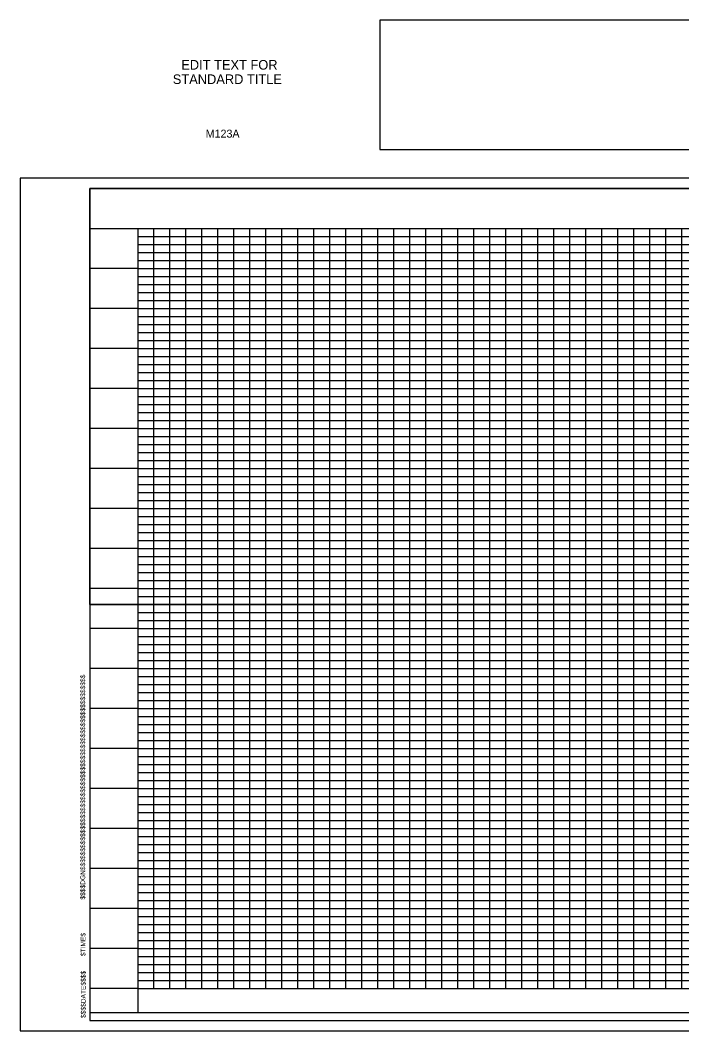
# Model space of a CAD drawing. Extents: x -87 to 1577, y -13 to 1250.
# Drawn here: x -87 to 740, y -13 to 1250 of the extents above; entities that cross this region are included whole.
import ezdxf

# ---------------------------------------------------------------- set-up
doc = ezdxf.new("R2010")
doc.units = 0
for name, color, linetype in [('D_CFL_Clip_Boundary_1', 7, 'Continuous'), ('D_CFL_Clip_Boundary_2', 7, 'Continuous'), ('D_CFL_Sheet_Border_ PlotShape', 7, 'Continuous'), ('D_CFL_Sheet_Border_Base', 7, 'Continuous'), ('D_CFL_Sheet_Border_Plan_Plan', 7, 'Continuous'), ('D_CFL_Sheet_Border_PnP', 7, 'Continuous'), ('D_CFL_Sheet_Border_Profile', 7, 'Continuous')]:
    doc.layers.add(name, color=color, linetype=linetype)

msp = doc.modelspace()

# ---------------------------------------------------------------- linework, layer by layer
at = {"layer": 'D_CFL_Clip_Boundary_1'}
msp.add_lwpolyline([(0, 520), (0, 1040), (1305, 1040), (1305, 1000), (1560, 1000), (1560, 520)], close=True, dxfattribs=at)
at = {"layer": 'D_CFL_Clip_Boundary_2'}
msp.add_lwpolyline([(1500, 520), (60, 520), (60, 40), (1500, 40)], close=True, dxfattribs=at)
at = {"layer": 'D_CFL_Sheet_Border_ PlotShape'}
msp.add_line((-86.9, -12.7), (-86.9, -12.7), dxfattribs=at)
msp.add_lwpolyline([(-86.9, -12.7), (1576.9, -12.7), (1576.9, 1052.6), (-86.9, 1052.6)], close=True, dxfattribs=at)
at = {"layer": 'D_CFL_Sheet_Border_Base'}
for points in [[(362.6, 1088.6), (1560, 1088.6), (1560, 1250.1), (362.6, 1250.1)], [(0, 0), (1560, 0), (1560, 1040), (0, 1040)]]:
    msp.add_lwpolyline(points, close=True, dxfattribs=at)
at = {"layer": 'D_CFL_Sheet_Border_Plan_Plan'}
msp.add_line((0, 520), (1560, 520), dxfattribs=at)
at = {"layer": 'D_CFL_Sheet_Border_PnP'}
for p, q in [((0, 520), (1560, 520)), ((60, 520), (60, 10)), ((80, 40), (80, 520)), ((100, 40), (100, 520)), ((120, 40), (120, 520)), ((140, 40), (140, 520)), ((160, 40), (160, 520)), ((180, 40), (180, 520)), ((200, 39.7), (200, 519.7)), ((220, 39.7), (220, 519.7)), ((240, 39.7), (240, 519.7)), ((260, 39.7), (260, 519.7)), ((280, 40), (280, 520)), ((300, 39.7), (300, 519.7)), ((320, 39.7), (320, 519.7)), ((340, 39.7), (340, 519.7)), ((360, 39.7), (360, 519.7)), ((380, 40), (380, 520)), ((400, 39.7), (400, 519.7)), ((420, 39.7), (420, 519.7)), ((440, 39.7), (440, 519.7)), ((460, 39.7), (460, 519.7)), ((480, 40), (480, 520)), ((500, 39.7), (500, 519.7)), ((520, 39.7), (520, 519.7)), ((540, 39.7), (540, 519.7)), ((560, 39.7), (560, 519.7)), ((580, 40), (580, 520)), ((600, 39.7), (600, 519.7)), ((620, 39.7), (620, 519.7)), ((640, 39.7), (640, 519.7)), ((660, 39.7), (660, 519.7)), ((680, 40), (680, 520)), ((700, 39.7), (700, 519.7)), ((720, 39.7), (720, 519.7)), ((60, 510), (1500, 510)), ((60, 500), (1500, 500)), ((60, 490), (0, 490)), ((60, 490), (1500, 490)), ((60, 480), (1500, 480)), ((60, 470), (1500, 470)), ((60, 460), (1500, 460)), ((60, 450), (1500, 450)), ((60, 440), (0, 440)), ((60, 440), (1500, 440)), ((60, 430), (1500, 430)), ((60, 420), (1500, 420)), ((60, 410), (1500, 410)), ((60, 400), (1500, 400)), ((60, 390), (0, 390)), ((60, 390), (1500, 390)), ((60, 380), (1500, 380)), ((60, 370), (1500, 370)), ((60, 360), (1500, 360)), ((60, 350), (1500, 350)), ((60, 340), (0, 340)), ((60, 340), (1500, 340)), ((60, 330), (1500, 330)), ((60, 320), (1500, 320)), ((60, 310), (1500, 310)), ((60, 300), (1500, 300)), ((60, 290), (0, 290)), ((60, 290), (1500, 290)), ((60, 280), (1500, 280)), ((60, 270), (1500, 270)), ((60, 260), (1500, 260)), ((60, 240), (0, 240)), ((60, 250), (1500, 250)), ((60, 240), (1500, 240)), ((60, 230), (1500, 230)), ((60, 220), (1500, 220)), ((60, 210), (1500, 210)), ((60, 190), (0, 190)), ((60, 200), (1500, 200)), ((60, 190), (1500, 190)), ((60, 180), (1500, 180)), ((60, 170), (1500, 170)), ((60, 160), (1500, 160)), ((60, 140), (0, 140)), ((60, 150), (1500, 150)), ((60, 140), (1500, 140)), ((60, 130), (1500, 130)), ((60, 120), (1500, 120)), ((60, 110), (1500, 110)), ((60, 90), (0, 90)), ((60, 100), (1500, 100)), ((60, 90), (1500, 90)), ((60, 80), (1500, 80)), ((60, 70), (1500, 70)), ((60, 60), (1500, 60)), ((60, 40), (0, 40)), ((60, 50), (1500, 50)), ((60, 40), (1500, 40)), ((0, 10), (1560, 10))]:
    msp.add_line(p, q, dxfattribs=at)
at = {"layer": 'D_CFL_Sheet_Border_Profile'}
for p, q in [((0, 990), (1560, 990)), ((60, 990), (60, 10)), ((80, 40), (80, 990)), ((100, 40), (100, 990)), ((120, 40), (120, 990)), ((140, 40), (140, 990)), ((160, 40), (160, 990)), ((180, 40), (180, 990)), ((200, 40), (200, 990)), ((220, 40), (220, 990)), ((240, 40), (240, 990)), ((260, 40), (260, 990)), ((280, 40), (280, 990)), ((300, 40), (300, 990)), ((320, 40), (320, 990)), ((340, 40), (340, 990)), ((360, 40), (360, 990)), ((380, 40), (380, 990)), ((400, 40), (400, 990)), ((420, 40), (420, 990)), ((440, 40), (440, 990)), ((460, 40), (460, 990)), ((480, 40), (480, 990)), ((500, 40), (500, 990)), ((520, 40), (520, 990)), ((540, 40), (540, 990)), ((560, 40), (560, 990)), ((580, 40), (580, 990)), ((600, 40), (600, 990)), ((620, 40), (620, 990)), ((640, 40), (640, 990)), ((660, 40), (660, 990)), ((680, 40), (680, 990)), ((700, 40), (700, 990)), ((720, 40), (720, 990)), ((740, 40), (740, 990)), ((60, 980), (1500, 980)), ((60, 970), (1500, 970)), ((60, 960), (1500, 960)), ((60, 950), (1500, 950)), ((60, 940), (0, 940)), ((60, 940), (1500, 940)), ((60, 930), (1500, 930)), ((60, 920), (1500, 920)), ((60, 910), (1500, 910)), ((60, 900), (1500, 900)), ((60, 890), (0, 890)), ((60, 890), (1500, 890)), ((60, 880), (1500, 880)), ((60, 870), (1500, 870)), ((60, 860), (1500, 860)), ((60, 850), (1500, 850)), ((60, 840), (0, 840)), ((60, 840), (1500, 840)), ((60, 830), (1500, 830)), ((60, 820), (1500, 820)), ((60, 810), (1500, 810)), ((60, 800), (1500, 800)), ((60, 790), (0, 790)), ((60, 790), (1500, 790)), ((60, 780), (1500, 780)), ((60, 770), (1500, 770)), ((60, 760), (1500, 760)), ((60, 750), (1500, 750)), ((60, 740), (0, 740)), ((60, 740), (1500, 740)), ((60, 730), (1500, 730)), ((60, 720), (1500, 720)), ((60, 710), (1500, 710)), ((60, 700), (1500, 700)), ((60, 690), (0, 690)), ((60, 690), (1500, 690)), ((60, 680), (1500, 680)), ((60, 670), (1500, 670)), ((60, 660), (1500, 660)), ((60, 650), (1500, 650)), ((60, 640), (0, 640)), ((60, 640), (1500, 640)), ((60, 630), (1500, 630)), ((60, 620), (1500, 620)), ((60, 610), (1500, 610)), ((60, 600), (1500, 600)), ((60, 590), (0, 590)), ((60, 590), (1500, 590)), ((60, 580), (1500, 580)), ((60, 570), (1500, 570)), ((60, 560), (1500, 560)), ((60, 550), (1500, 550)), ((60, 540), (0, 540)), ((60, 540), (1500, 540)), ((60, 530), (1500, 530)), ((60, 520), (1500, 520)), ((60, 510), (1500, 510)), ((60, 500), (1500, 500)), ((60, 490), (0, 490)), ((60, 490), (1500, 490)), ((60, 480), (1500, 480)), ((60, 470), (1500, 470)), ((60, 460), (1500, 460)), ((60, 450), (1500, 450)), ((60, 440), (0, 440)), ((60, 440), (1500, 440)), ((60, 430), (1500, 430)), ((60, 420), (1500, 420)), ((60, 410), (1500, 410)), ((60, 400), (1500, 400)), ((60, 390), (0, 390)), ((60, 390), (1500, 390)), ((60, 380), (1500, 380)), ((60, 370), (1500, 370)), ((60, 360), (1500, 360)), ((60, 350), (1500, 350)), ((60, 340), (0, 340)), ((60, 340), (1500, 340)), ((60, 330), (1500, 330)), ((60, 320), (1500, 320)), ((60, 310), (1500, 310)), ((60, 300), (1500, 300)), ((60, 290), (0, 290)), ((60, 290), (1500, 290)), ((60, 280), (1500, 280)), ((60, 270), (1500, 270)), ((60, 260), (1500, 260)), ((60, 240), (0, 240)), ((60, 250), (1500, 250)), ((60, 240), (1500, 240)), ((60, 230), (1500, 230)), ((60, 220), (1500, 220)), ((60, 210), (1500, 210)), ((60, 190), (0, 190)), ((60, 200), (1500, 200)), ((60, 190), (1500, 190)), ((60, 180), (1500, 180)), ((60, 170), (1500, 170)), ((60, 160), (1500, 160)), ((60, 140), (0, 140)), ((60, 150), (1500, 150)), ((60, 140), (1500, 140)), ((60, 130), (1500, 130)), ((60, 120), (1500, 120)), ((60, 110), (1500, 110)), ((60, 90), (0, 90)), ((60, 100), (1500, 100)), ((60, 90), (1500, 90)), ((60, 80), (1500, 80)), ((60, 70), (1500, 70)), ((60, 60), (1500, 60)), ((60, 40), (0, 40)), ((60, 50), (1500, 50)), ((60, 40), (1500, 40)), ((0, 10), (1560, 10))]:
    msp.add_line(p, q, dxfattribs=at)

# ---------------------------------------------------------------- texts
at = {"layer": 'D_CFL_Sheet_Border_Base'}
for s, height, p in [('EDIT TEXT FOR', 12, (114.4, 1188.4)), ('STANDARD TITLE', 12, (103.8, 1170.4)), ('M123A', 10, (144.9, 1103.4))]:
    msp.add_text(s, height=height, dxfattribs=at).set_placement(p)
for s, p in [('$$$$DGN$$$$$$$$$$$$$$$$$$$$$$$$$$$$$$$$$$$$$$$$$$$$$$$$$$$$$', (-5.7, 151.3)), ('$TIME$', (-5.3, 80.6)), ('$$$$DATE$$$$', (-5.1, 3.3))]:
    msp.add_text(s, height=6, rotation=90, dxfattribs=at).set_placement(p)

doc.saveas('drawing.dxf')
